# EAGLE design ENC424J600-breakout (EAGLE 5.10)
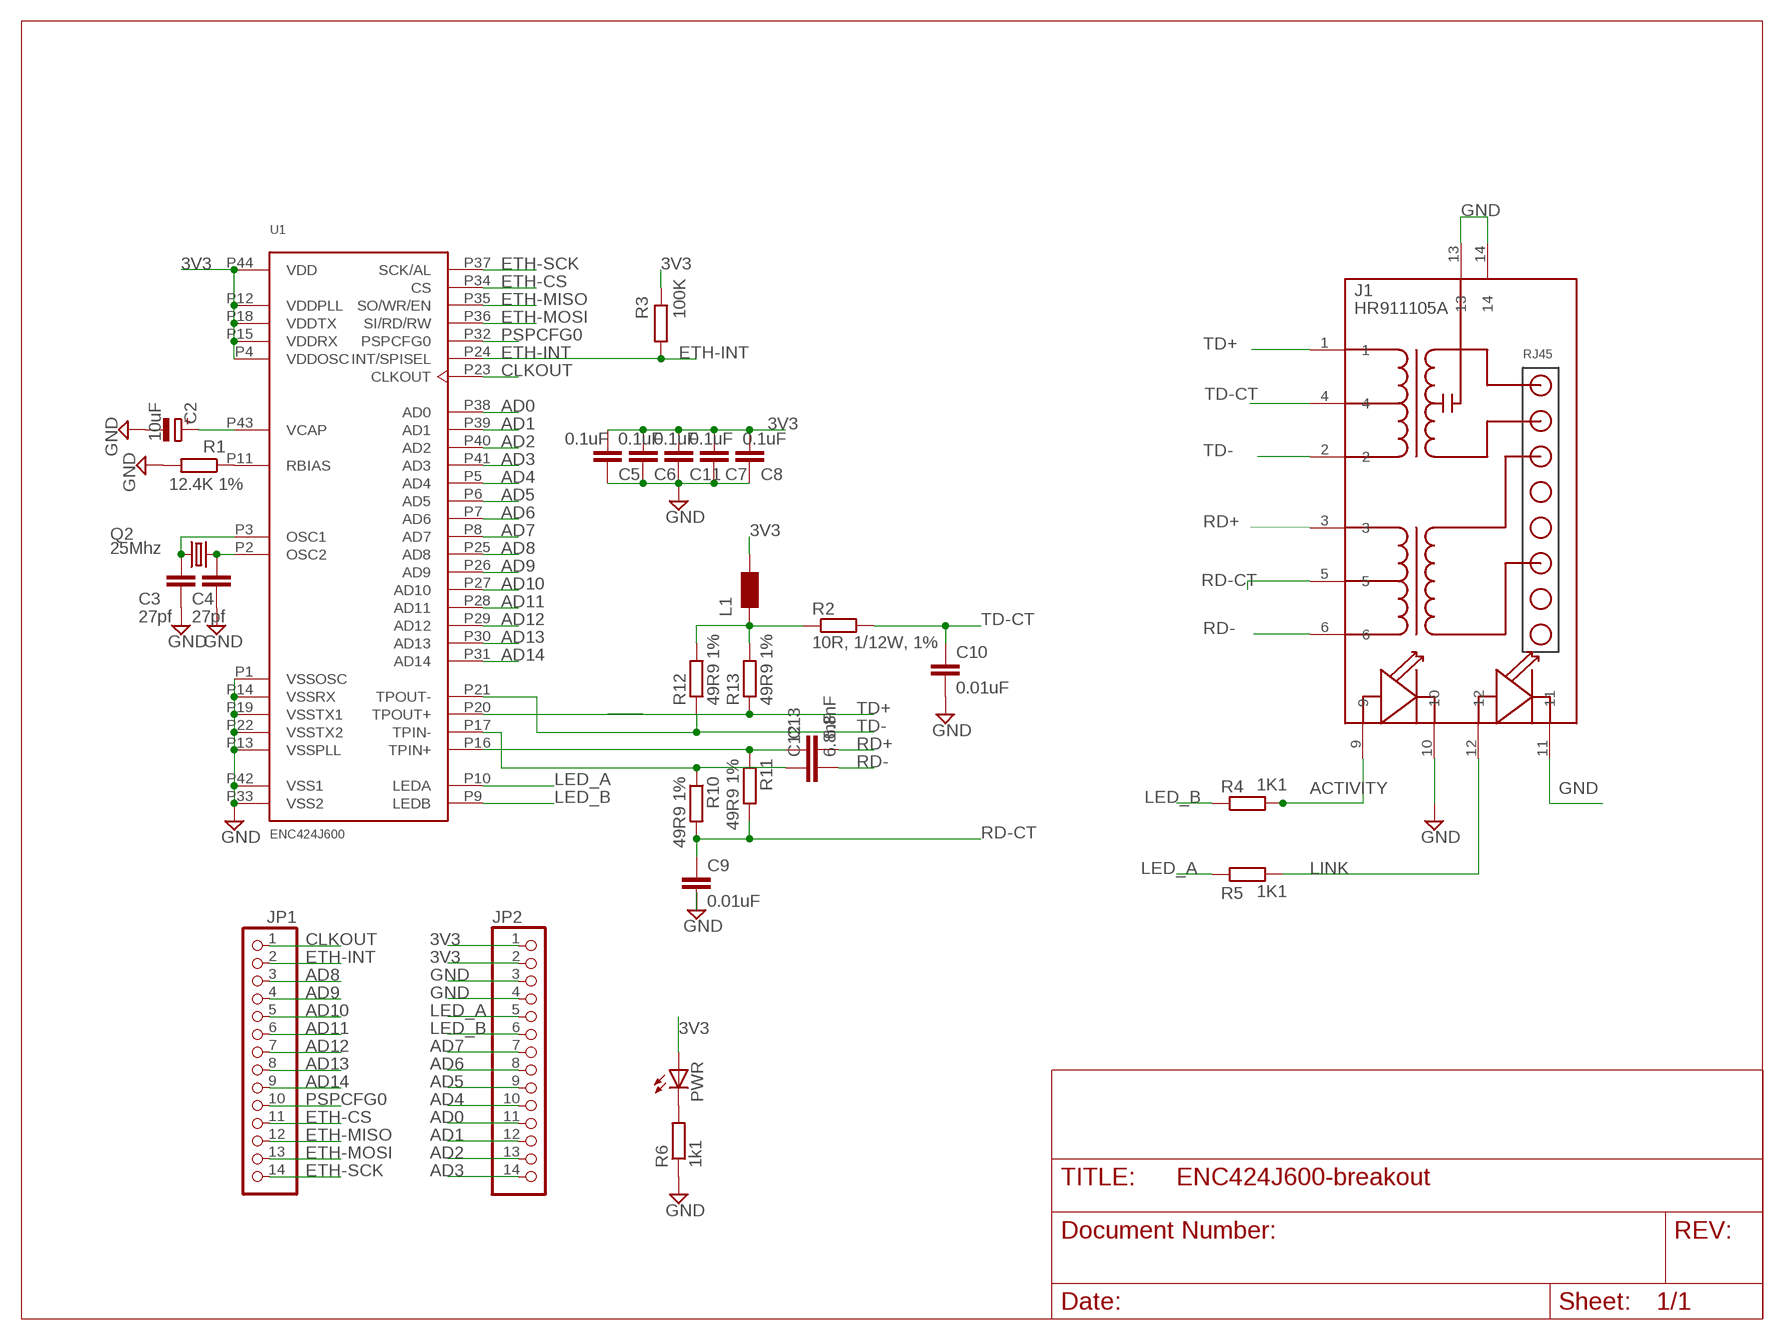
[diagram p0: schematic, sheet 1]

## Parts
C2  10uF  CPOL-EUSMCA  [SMC_A]
C3  27pf  C-EUC0603  [C0603]
C4  27pf  C-EUC0603  [C0603]
C5  0.1uF  C-EUC0603  [C0603]
C6  0.1uF  C-EUC0603  [C0603]
C7  0.1uF  C-EUC0603  [C0603]
C8  0.1uF  C-EUC0603  [C0603]
C9  0.01uF  C-EUC0603  [C0603]
C10  0.01uF  C-EUC0603  [C0603]
C11  0.1uF  C-EUC0603  [C0603]
C12  6.8nF  C-EUC0603  [C0603]
C13  6.8nF  C-EUC0603  [C0603]
J1  HR911105A  [HR911105A]
JP1  PINHD-1X14  [1X14]
JP2  PINHD-1X14  [1X14]
L1  WE-KIL_0805  [WE-KI_0805_B]
PWR  LED805  [LED-805]
Q2  25Mhz  CRYSTALHC49UP  [HC49UP]
R1  12.4K 1%  R-EU_R0603  [R0603]
R2  10R, 1/12W, 1%  R-EU_R0603  [R0603]
R3  100K  R-EU_R0603  [R0603]
R4  1K1  R-EU_R0603  [R0603]
R5  1K1  R-EU_R0603  [R0603]
R6  1k1  R-EU_R0603  [R0603]
R10  49R9 1%  R-EU_R0603  [R0603]
R11  49R9 1%  R-EU_R0603  [R0603]
R12  49R9 1%  R-EU_R0603  [R0603]
R13  49R9 1%  R-EU_R0603  [R0603]
U1  ENC424J600  [TQFP44]

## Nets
3V3: C5.1 C6.1 C7.1 C8.1 C11.1 JP2.1 JP2.2 L1.1 PWR.A R3.1 U1.P4(VDDOSC) U1.P12(VDDPLL) U1.P15(VDDRX) U1.P18(VDDTX) U1.P44(VDD)
ACTIVITY: J1.9 R4.2
AD0: JP2.11 U1.P38(AD0)
AD1: JP2.12 U1.P39(AD1)
AD2: JP2.13 U1.P40(AD2)
AD3: JP2.14 U1.P41(AD3)
AD4: JP2.10 U1.P5(AD4)
AD5: JP2.9 U1.P6(AD5)
AD6: JP2.8 U1.P7(AD6)
AD7: JP2.7 U1.P8(AD7)
AD8: JP1.3 U1.P25(AD8)
AD9: JP1.4 U1.P26(AD9)
AD10: JP1.5 U1.P27(AD10)
AD11: JP1.6 U1.P28(AD11)
AD12: JP1.7 U1.P29(AD12)
AD13: JP1.8 U1.P30(AD13)
AD14: JP1.9 U1.P31(AD14)
CCT: L1.2 R2.1 R12.2 R13.2
CLKOUT: JP1.1 U1.P23(CLKOUT)
DSFGDF: C12.1 R10.1 U1.P17(TPIN-)
DSGDFSG: C13.1 R11.1 U1.P16(TPIN+)
ETH-CS: JP1.11 U1.P34(CS)
ETH-INT: JP1.2 R3.2 U1.P24(INT/SPISEL)
ETH-MISO: JP1.12 U1.P35(SO/WR/EN)
ETH-MOSI: JP1.13 U1.P36(SI/RD/RW)
ETH-SCK: JP1.14 U1.P37(SCK/AL)
GND: C2.- C3.2 C4.2 C5.2 C6.2 C7.2 C8.2 C9.2 C10.2 C11.2 J1.10 J1.11 J1.13 J1.14 JP2.3 JP2.4 R1.2 R6.1 U1.P1(VSSOSC) U1.P13(VSSPLL) U1.P14(VSSRX) U1.P19(VSSTX1) U1.P22(VSSTX2) U1.P33(VSS2) U1.P42(VSS1)
LED_A: JP2.5 R5.1 U1.P10(LEDA)
LED_B: JP2.6 R4.1 U1.P9(LEDB)
LINK: J1.12 R5.2
N$1: C2.+ U1.P43(VCAP)
N$2: R1.1 U1.P11(RBIAS)
N$3: PWR.C R6.2
N$4: C3.1 Q2.1 U1.P3(OSC1)
N$8: C4.1 Q2.2 U1.P2(OSC2)
PSPCFG0: JP1.10 U1.P32(PSPCFG0)
RD+: C13.2 J1.3
RD-: C12.2 J1.6
RD-CT: C9.1 J1.5 R10.2 R11.2
TD+: J1.1 R13.1 U1.P20(TPOUT+)
TD-: J1.2 R12.1 U1.P21(TPOUT-)
TD-CT: C10.1 J1.4 R2.2

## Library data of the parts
C2 = rcl:CPOL-EU: POLARIZED CAPACITOR, European symbol
C3-C13 = rcl:C-EU: CAPACITOR, European symbol
J1 = CONNECTER:HR911105A
JP1 JP2 = pinhead - Copy:PINHD-1X14: PIN HEADER
L1 = wuerth-elektronik:WE-KIL: SMD Wire Wound Ceramic Inductor WE-KIL
PWR = dp_devices:LED
Q2 = crystal:CRYSTAL: CRYSTAL
R1-R6 R10-R13 = rcl:R-EU_: RESISTOR, European symbol
U1 = dp_devices:ENC424J600: Stand-Alone 10/100 Ethernet Controller with SPI or Parallel Interface Source: http://ww1.microchip.com/downloads/en/DeviceDoc/39935c.pdf

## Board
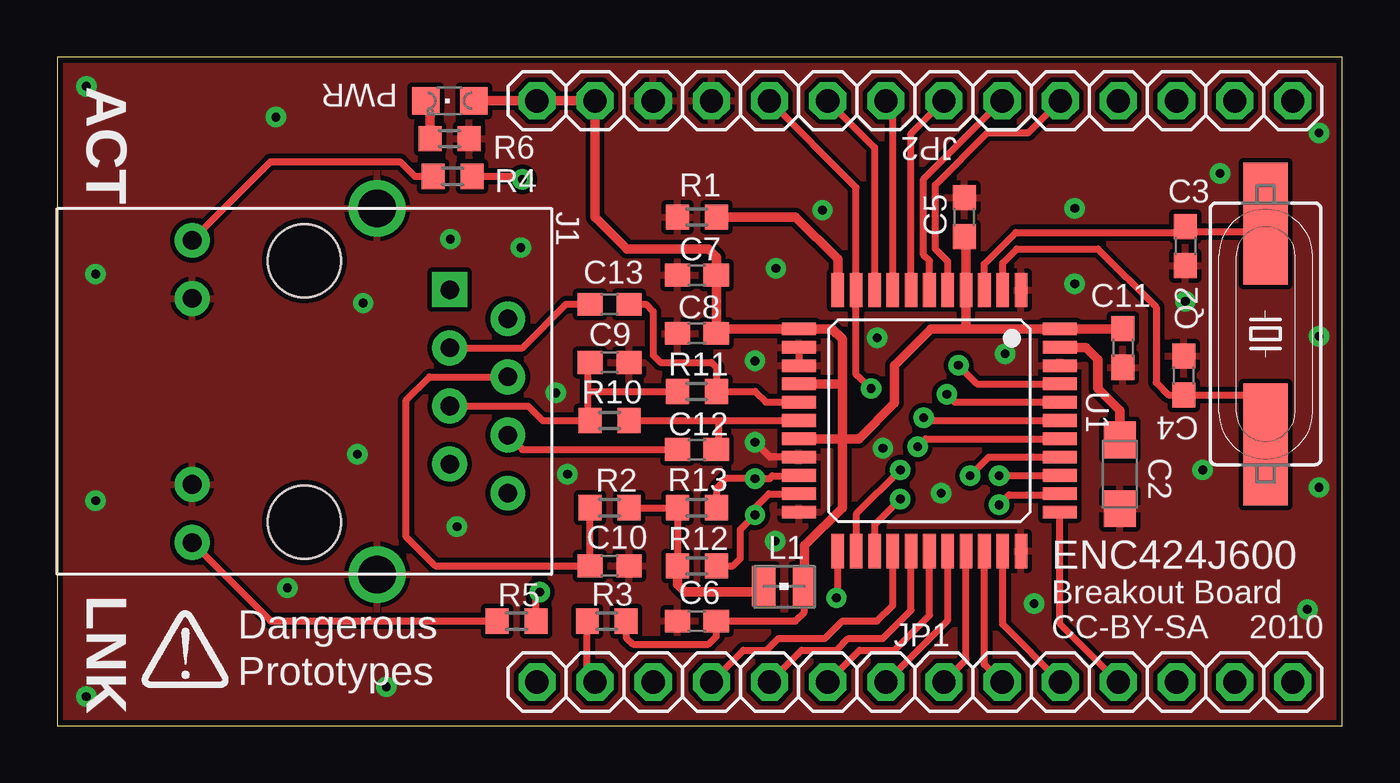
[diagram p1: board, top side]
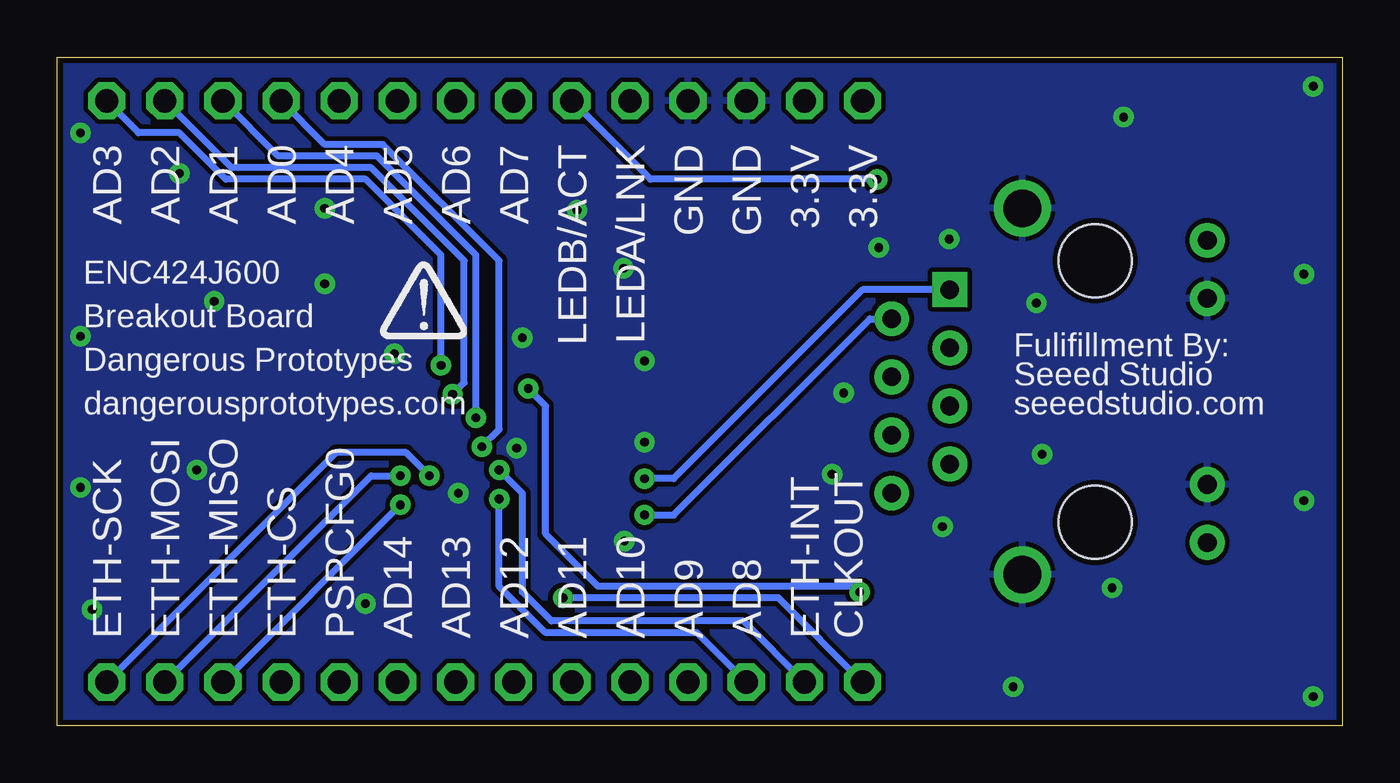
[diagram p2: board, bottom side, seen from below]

Size 56.13 x 29.21 mm. Coordinates in mm from the lower left corner, seen from the top.
Outline: 0,0 56.13,0 56.13,29.21 0,29.21 0,0
Copper layers (1*16): Top 0.035mm / dielectric 1.5mm / Bottom 0.035mm
Design rules "SparkFun *": minimum track width 8mil, minimum drill 15mil, track to track 8mil, track to pad 8mil, pad to pad 8mil, via to via 8mil, smd to smd 8mil, copper to edge 10mil, drill to drill 8mil, minimum pad ring 12mil, minimum via ring 10mil, stop-mask expansion 4mil, vias tented up to drill 25mil, thermal gap 8mil

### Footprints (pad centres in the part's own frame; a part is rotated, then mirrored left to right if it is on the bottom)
SMC_A = smd 1.6 x 1.4: + -1.5,0; - 1.5,0
C0603 = smd 1.1 x 1: 1 -0.85,0; 2 0.85,0
HR911105A = drill 0.813 pad 1.524 square: 1 4.445,-6.35 | drill 0.813 pad 1.524 round: 2 3.175,-8.89; 3 1.905,-6.35; 4 0.635,-8.89; 5 -0.635,-6.35; 6 -1.905,-8.89; 7 -3.175,-6.35; 8 -4.445,-8.89; 9 6.604,4.902; 10 4.064,4.902; 11 -4.064,4.902; 12 -6.604,4.902 | drill 1.651 pad 2.159 round: 13 8.001,-3.175; 14 -8.001,-3.175 | hole 3.2: 5.715,0; -5.715,0
1X14 = drill 1.016 octagon: 1 -16.51,0; 2 -13.97,0; 3 -11.43,0; 4 -8.89,0; 5 -6.35,0; 6 -3.81,0; 7 -1.27,0; 8 1.27,0; 9 3.81,0; 10 6.35,0; 11 8.89,0; 12 11.43,0; 13 13.97,0; 14 16.51,0
WE-KI_0805_B = smd 1.02 x 1.78: 1 -0.89,0; 2 0.89,0
LED-805 = smd 1.2 x 1.2: A 0,-1.05; C 0,1.05
HC49UP = smd 5.334 x 1.93: 1 -4.826,0; 2 4.826,0
R0603 = smd 1 x 1.1: 1 -0.85,0; 2 0.85,0
TQFP44 = smd 0.55 x 1.5: P1 -4,-5.7; P2 -3.2,-5.7; P3 -2.4,-5.7; P4 -1.6,-5.7; P5 -0.8,-5.7; P6 0,-5.7; P7 0.8,-5.7; P8 1.6,-5.7; P9 2.4,-5.7; P10 3.2,-5.7; P11 4,-5.7; P23 4,5.7; P24 3.2,5.7; P25 2.4,5.7; P26 1.6,5.7; P27 0.8,5.7; P28 0,5.7; P29 -0.8,5.7; P30 -1.6,5.7; P31 -2.4,5.7; P32 -3.2,5.7; P33 -4,5.7 | smd 1.5 x 0.55: P12 5.7,-4; P13 5.7,-3.2; P14 5.7,-2.4; P15 5.7,-1.6; P16 5.7,-0.8; P17 5.7,0; P18 5.7,0.8; P19 5.7,1.6; P20 5.7,2.4; P21 5.7,3.2; P22 5.7,4; P34 -5.7,4; P35 -5.7,3.2; P36 -5.7,2.4; P37 -5.7,1.6; P38 -5.7,0.8; P39 -5.7,0; P40 -5.7,-0.8; P41 -5.7,-1.6; P42 -5.7,-2.4; P43 -5.7,-3.2; P44 -5.7,-4

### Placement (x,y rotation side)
C2  46.42,10.99 270 top
C3  49.28,20.95 270 top
C4  49.21,15.3 90 top
C5  39.62,22.23 90 top
C6  27.94,4.57 180 top
C7  27.94,19.68 180 top
C8  27.94,17.14 180 top
C9  24.13,15.88 0 top
C10  24.13,6.99 0 top
C11  46.55,16.51 270 top
C12  27.94,12.06 180 top
C13  24.13,18.41 180 top
J1  10.79,14.61 90 top
JP1  37.47,1.91 0 top
JP2  37.47,27.3 0 top
L1  31.75,6.1 180 top
PWR  17.14,27.3 90 top
Q2  52.78,17.12 270 top
R1  27.94,22.23 180 top
R2  24.13,9.53 180 top
R3  24,4.57 180 top
R4  17.27,24 180 top
R5  20.07,4.57 180 top
R6  17.14,25.65 180 top
R10  24.13,13.34 180 top
R11  27.94,14.61 180 top
R12  27.94,6.99 180 top
R13  27.94,9.53 180 top
U1  38.1,13.34 180 top
U$1  [DP_LOGO]  5.59,2.29 0 top
U$2  [DP_LOGO]  40.13,17.53 0 bottom

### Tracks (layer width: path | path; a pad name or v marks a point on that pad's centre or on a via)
3V3
  Top 0.305: U1.P12 32.39,17.35 | L1.1 32.64,4.95 32.26,4.57 C6.1 28.79,3.9 28.45,3.56 25.15,3.56 24.85,3.85 R3.1
  Top 0.406: 34.29,12.54 U1.P18 | 34.29,12.54 35.01,12.54 36.58,14.1 36.58,15.75 38.16,17.34 39.76,17.34 | 34.29,14.86 34.29,16.89 33.85,17.34 U1.P12 28.98,17.34 C8.1 C7.1 28.79,20.49 28.45,20.83 24.89,20.83 23.5,22.23 JP2.2 JP2.1 PWR.A | U1.P15 34.21,14.94 34.29,14.86 | 39.76,17.34 U1.P44 46.52,17.34 C11.1 | 39.76,17.34 39.7,17.4 U1.P4 39.7,21.3 C5.1 | 34.29,12.54 34.29,9.53 32.64,7.88 L1.1 | 34.29,12.54 34.29,14.86
ACTIVITY
  Top 0.305: R4.2 15.62,24 14.99,24.64 9.32,24.64 J1.9
AD0  (via drill 0.38)
  Top 0.305: U1.P38 37.94,12.54 v37.59,12.19
  Bottom 0.305: JP2.11 44.45,25.4 41.91,25.4 36.83,20.32 36.83,12.95 v37.59,12.19
AD1  (via drill 0.38)
  Top 0.305: U1.P39 37.97,13.34 v37.85,13.46
  Bottom 0.305: JP2.12 46.48,24.89 42.16,24.89 37.85,20.57 v37.85,13.46
AD2  (via drill 0.38)
  Top 0.305: U1.P40 39.2,14.13 v38.86,14.48
  Bottom 0.305: JP2.13 48.51,24.38 42.42,24.38 38.35,20.32 38.35,14.99 v38.86,14.48
AD3  (via drill 0.38)
  Top 0.305: U1.P41 40.18,14.94 v39.37,15.75
  Bottom 0.305: JP2.14 52.58,25.91 50.8,25.91 48.77,23.88 42.67,23.88 39.37,20.57 v39.37,15.75
AD4
  Top 0.305: U1.P5 38.9,20.28 38.35,20.83 38.35,23.62 40.64,25.91 42.42,25.91 JP2.10
AD5
  Top 0.305: U1.P6 38.1,20.32 37.85,20.57 37.85,23.88 JP2.9
AD6
  Top 0.305: U1.P7 37.3,25.87 JP2.8
AD7
  Top 0.305: U1.P8 36.5,27 JP2.7
AD8  (via drill 0.38)
  Top 0.305: U1.P25 35.7,8.78 v36.83,9.91
  Bottom 0.305: v36.83,9.91 36.83,6.1 34.8,4.06 28.19,4.06 JP1.3
AD9
  Top 0.305: JP1.4 29.97,3.3 30.99,3.3 31.5,3.81 33.53,3.81 34.29,4.57 35.81,4.57 36.5,5.26 U1.P26
AD10
  Top 0.305: U1.P27 37.3,5.04 36.07,3.81 34.54,3.81 34.04,3.3 32.51,3.3 JP1.5
AD11
  Top 0.305: U1.P28 38.1,4.83 36.58,3.3 35.05,3.3 JP1.6
AD12
  Top 0.305: U1.P29 38.9,4.61 JP1.7
AD13
  Top 0.305: U1.P30 39.7,2.87 JP1.8
AD14
  Top 0.305: U1.P31 40.5,2.68 JP1.9
CCT
  Top 0.305: R2.1 R13.2 R12.2
  Top 0.406: L1.2 31.11,5.97 30.99,5.84 27.43,5.84 27.09,6.18 R12.2
CLKOUT  (via drill 0.38)
  Top 0.305: U1.P23 34.1,5.91 v34.04,5.59
  Bottom 0.305: v34.04,5.59 24.64,5.59 JP1.1
DSFGDF
  Top 0.305: R10.1 28.89,13.34 | 28.89,13.34 U1.P17 | 28.89,13.34 28.89,12.17 C12.1
DSGDFSG
  Top 0.305: U1.P16 30.95,14.13 30.48,14.61 R11.1 28.79,15.66 28.57,15.88 26.35,15.88 26.04,16.19 26.04,18.1 25.72,18.41 C13.1
ETH-CS
  Top 0.305: U1.P34 43.8,4.46 JP1.11
ETH-INT  (via drill 0.38)
  Top 0.305: U1.P24 34.9,9.25 v36.83,11.18 | R3.2 23.15,2.25 JP1.2
  Bottom 0.305: v36.83,11.18 35.81,10.16 35.81,5.84 34.54,4.57 26.16,4.57 JP1.2
ETH-MISO  (via drill 0.38)
  Top 0.305: U1.P35 43.85,10.09 41.58,10.09 v41.15,9.65
  Bottom 0.305: JP1.12 v41.15,9.65
ETH-MOSI  (via drill 0.38)
  Top 0.305: U1.P36 41.16,10.94 v41.15,10.92
  Bottom 0.305: v41.15,10.92 42.42,10.92 JP1.13
ETH-SCK  (via drill 0.38)
  Top 0.305: U1.P37 40.69,11.73 v39.88,10.92
  Bottom 0.305: v39.88,10.92 40.89,11.94 43.94,11.94 JP1.14
GND  (via drill 0.38)
  Top 0.305: U1.P19 31.13,11.73 v30.48,12.38 | U1.P13 32.4,15.89 32.38,15.88
  other vias: 20.26,20.89 30.48,15.94 33.43,22.53 31.37,8.06 21.78,14.54 17.46,8.7 22.29,10.99 31.39,19.99 49.28,18.54 55.12,17.02 54.61,5.08 1.27,1.27 1.27,27.94 50.8,24.13 44.45,19.3 41.4,16.26 38.61,10.16 42.67,5.33 44.45,22.61 55.12,25.91 50.04,11.18 55.12,10.41 9.55,26.59 17.17,21.26 10.06,6.02 14.38,1.7 13.36,18.47 13.11,11.86 1.68,9.83 1.68,19.74 35.81,16.95 36.07,12.13
  pour Top: 0,29.21 55.88,29.21 55.88,0 0,0
  pour Bottom: 0,29.21 55.88,29.21 55.88,0 0,0
LED_A  (via drill 0.38)
  Top 0.305: JP2.5 34.9,23.52 U1.P10 34.9,15.34 v35.56,14.73 | R5.1 20.92,5.68 v21.08,5.84
  Bottom 0.305: v21.08,5.84 21.34,6.1 32.51,6.1 34.8,8.38 34.8,13.97 v35.56,14.73
LED_B  (via drill 0.38)
  Top 0.305: U1.P9 35.7,25.26 JP2.6 | R4.1 20.19,24 v20.32,23.88
  Bottom 0.305: v20.32,23.88 30.23,23.88 JP2.6
LINK
  Top 0.305: R5.2 9.32,4.57 J1.12
N$1
  Top 0.406: C2.+ 46.42,13.78 45.47,14.73 45.47,16 44.93,16.54 U1.P43
N$2
  Top 0.406: U1.P11 34.1,20.38 32.26,22.23 R1.1
N$3
  Top 0.406: R6.2 16.3,27.11 PWR.C
N$4
  Top 0.305: U1.P3 40.5,20.18 41.87,21.55 49.02,21.55 C3.1 49.49,21.59 52.58,21.59 52.78,21.79 Q2.1
N$8
  Top 0.305: U1.P2 41.3,20.22 41.91,20.83 45.47,20.83 48.01,18.29 48.01,14.99 48.54,14.45 C4.1 52.35,14.45 52.58,14.22 52.58,12.5 Q2.2
PSPCFG0
  Top 0.305: U1.P32 41.3,4.42 JP1.10
RD+
  Top 0.305: C13.2 22.23,18.41 20.32,16.51 J1.3
RD-
  Top 0.305: C12.2 20.32,12.06 J1.6
RD-CT
  Top 0.305: 23.18,14.61 R11.2 | C9.1 23.18,15.88 23.18,14.61 | 23.18,14.61 23.18,13.34 R10.2 21.21,13.34 20.57,13.97 J1.5
TD+  (via drill 0.38)
  Top 0.305: U1.P20 32.39,10.92 31.24,10.92 31.11,10.79 v30.48,10.79 29.21,10.79 28.79,10.38 R13.1
  Bottom 0.305: v30.48,10.79 29.21,10.79 20.95,19.05 J1.1
TD-  (via drill 0.38)
  Top 0.305: U1.P21 | U1.P21 31.09,10.13 30.48,9.53 v30.48,9.21 29.84,8.57 29.84,7.3 29.53,6.99 R12.1
  Bottom 0.305: v30.48,9.21 29.21,9.21 20.64,17.78 J1.2
TD-CT
  Top 0.305: R2.2 C10.1 16.51,6.99 15.24,8.26 15.24,14.22 16.26,15.24 J1.4

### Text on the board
tNames: ACT | ENC424J600 | LNK | Breakout Board | Dangerous | CC-BY-SA | 2010 | Prototypes
bNames: 3.3V | 3.3V | GND | GND | LEDA/LNK | LEDB/ACT | AD7 | AD6 | AD5 | AD4 | AD0 | AD1 | AD2 | AD3 | ENC424J600 | Breakout Board | Fulifillment By: | Seeed Studio | Dangerous Prototypes | seeedstudio.com | dangerousprototypes.com | CLKOUT | ETH-INT | AD8 | AD9 | AD10 | AD11 | AD12 | AD13 | AD14 | PSPCFG0 | ETH-CS | ETH-MISO | ETH-MOSI | ETH-SCK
